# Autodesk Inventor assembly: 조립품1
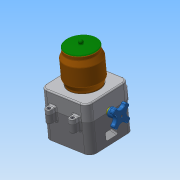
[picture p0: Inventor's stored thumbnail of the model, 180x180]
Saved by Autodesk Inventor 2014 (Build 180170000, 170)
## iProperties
Created: 2018-01
Part Number: 조립품1
Document SubType Name: Assembly
Designer: Administrator
Author: Administrator
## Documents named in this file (9)
- C:\Users\Administrator\Desktop\480107V1029\조립품1.iam
- C:\Users\Administrator\Desktop\480107V1029\본체.ipt
- C:\Users\Administrator\Desktop\480107V1029\본체커버.ipt
- C:\Users\Administrator\Desktop\480107V1029\핸들축.ipt
- C:\Users\Administrator\Desktop\480107V1029\핸들.ipt
- C:\Users\Administrator\Desktop\480107V1029\용기.ipt
- C:\Users\Administrator\Desktop\480107V1029\용기캡.ipt
- C:\Users\Administrator\Desktop\480107V1029\볼트 M3x12.ipt
- C:\Users\Administrator\Desktop\480107V1029\볼트 M4x12.ipt
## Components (2 placed, 2 different names)
1. 핸들:1
2. 핸들축:1
